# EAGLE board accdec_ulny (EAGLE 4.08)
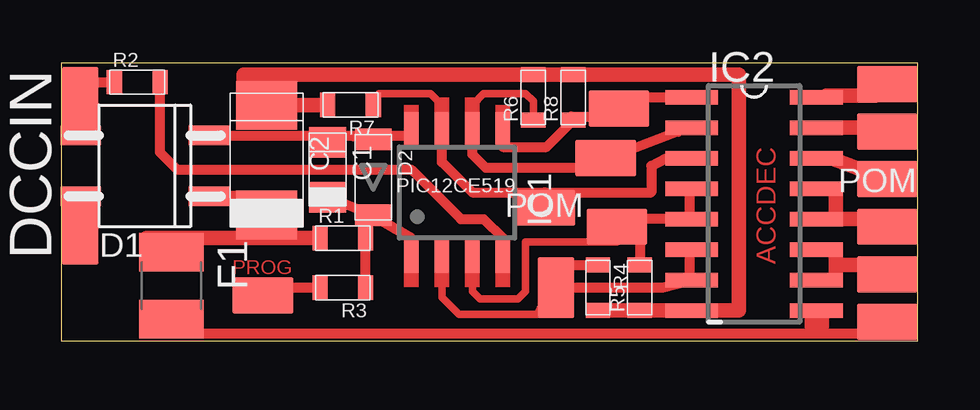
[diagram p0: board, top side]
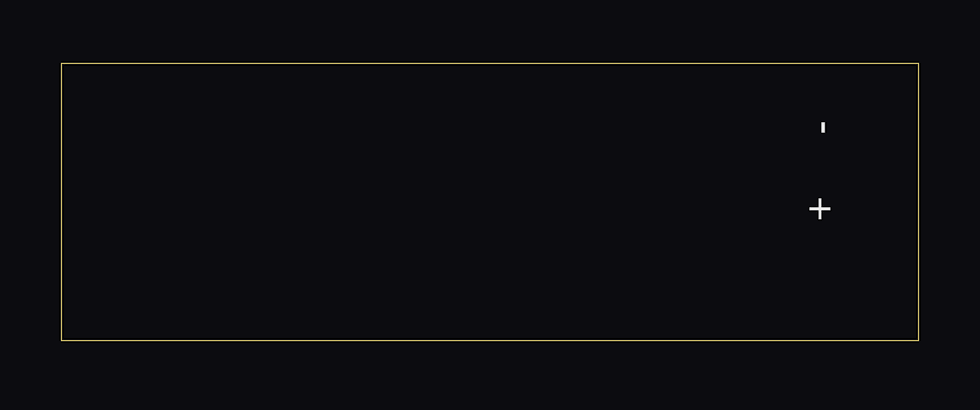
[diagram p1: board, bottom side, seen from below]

Size 35.71 x 11.58 mm. Coordinates in mm from the lower left corner, seen from the top.
Outline: 0,0 35.71,0 35.71,11.58 0,11.58 0,0
Copper layers used: Top

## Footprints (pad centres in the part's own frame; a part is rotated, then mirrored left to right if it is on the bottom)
CON_1*0.6 = smd 2.54 x 1.524: P$1 0,0
CA = smd 1.27 x 1.524: P$1 -1.143,0; P$2 1.143,0
CC = smd 2.032 x 2.54: P$1 -2.286,0; P$2 2.286,0
G1 = smd 1.676 x 0.813: 1 3.302,-1.27; 2 3.302,1.27; 3 -2.032,1.27; 4 -2.032,-1.27
ZMM = smd 0.889 x 1.524: P$1 -1.587,0; P$2 1.587,0
1210 = smd 1.6 x 2.7: 1 -1.4,0; 2 1.4,0
SO8/SN = smd 0.61 x 1.524: 1 -1.905,-2.6; 2 -0.635,-2.6; 3 0.635,-2.6; 4 1.905,-2.6; 5 1.905,2.6; 6 0.635,2.6; 7 -0.635,2.6; 8 -1.905,2.6
SO16 = smd 0.6 x 2.2: 1 -4.445,-2.6; 2 -3.175,-2.6; 3 -1.905,-2.6; 4 -0.635,-2.6; 5 0.635,-2.6; 6 1.905,-2.6; 7 3.175,-2.6; 8 4.445,-2.6; 9 4.445,2.6; 10 3.175,2.6; 11 1.905,2.6; 12 0.635,2.6; 13 -0.635,2.6; 14 -1.905,2.6; 15 -3.175,2.6; 16 -4.445,2.6
MICRO_MELF = smd 0.635 x 1.016: P$1 -0.953,0; P$2 0.953,0

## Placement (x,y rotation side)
+5V  [CON_1*0.6]  8.41,1.9 0 top
+12V  [CON_1*0.6]  34.44,0.79 0 top
C1  2.2µF 6v  [CA]  11.11,7.14 270 top
C2  10µF 25v  [CC]  8.57,7.54 270 top
D1  MB6S  [G1]  2.85,7.3 0 top
D2  5.1v  [ZMM]  13.01,6.82 270 top
DCCIN1  [CON_1*0.6]  0.79,10.15 90 top
DCCIN2  [CON_1*0.6]  0.79,4.44 90 top
F1  500mA  [1210]  4.6,2.3 270 top
IC1  PIC12CE519  [SO8/SN]  16.5,6.19 0 top
IC2  ULN2003A  [SO16]  28.89,5.71 270 top
OUT0  [CON_1*0.6]  34.44,6.74 0 top
OUT1  [CON_1*0.6]  34.44,8.73 0 top
OUT2  [CON_1*0.6]  34.44,10.71 0 top
OUT4  [CON_1*0.6]  34.44,4.76 0 top
OUT5  [CON_1*0.6]  34.44,2.77 0 top
P0  [CON_1*0.6]  20.15,5.55 0 top
P1  [CON_1*0.6]  22.7,7.62 0 top
P2  [CON_1*0.6]  23.25,9.68 0 top
P4  [CON_1*0.6]  23.17,4.76 0 top
P5  [CON_1*0.6]  20.63,2.22 90 top
R1  680  [MICRO_MELF]  11.74,4.28 0 top
R2  100k  [MICRO_MELF]  3.17,10.79 0 top
R3  1k  [MICRO_MELF]  11.74,2.22 180 top
R4  100k  [MICRO_MELF]  22.38,2.22 270 top
R5  100k  [MICRO_MELF]  24.12,2.22 90 top
R6  100k  [MICRO_MELF]  19.68,10.15 90 top
R7  100k  [MICRO_MELF]  12.06,9.84 180 top
R8  100k  [MICRO_MELF]  21.35,10.15 90 top

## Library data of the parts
+5V +12V C1 C2 D1 D2 DCCIN1 DCCIN2 F1 IC1 IC2 OUT0 OUT1 OUT2 OUT4 OUT5 P0 P1 P2 P4 P5 R1-R8 = NMRA-DCC_Decoder_Parts

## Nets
+: C2.P$2 D1.1 F1.1 R1.P$1
DCCIN: IC1.4 R2.P$2
GND: IC2.8 R4.P$2 R5.P$1 R6.P$2 R8.P$2
GP0: IC1.7 P0.P$1 R7.P$1
GP1: IC1.6 R6.P$1
GP2: IC1.5 R8.P$1
GP4: IC1.3 P4.P$1 R5.P$2
GP5: IC1.2 IC2.7 P5.P$1 R4.P$1
N$1: D1.3 DCCIN1.P$1 R2.P$1
N$2: D1.4 DCCIN2.P$1
N$3: +5V.P$1 R3.P$2
N$4: +12V.P$1 F1.2
N$10: OUT0.P$1
N$12: OUT5.P$1
N$14: IC2.14
S$2: IC2.16
S$3: IC2.13
S$8: IC2.4
S$15: C1.P$1 D2.P$1 IC1.8
S$16: C2.P$1 R7.P$2
VCC: C1.P$2 D2.P$2 IC1.1 R1.P$2 R3.P$1

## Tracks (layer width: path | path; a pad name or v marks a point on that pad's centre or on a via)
+
  Top 0.406: 6.58,5.95 D1.1 | F1.1 3.57,4.28 | 8.49,4.28 C2.P$2 8.49,5.95 8.49,4.28
  Top 0.61: 8.49,5.95 6.58,5.95 | 3.57,4.28 8.49,4.28 R1.P$1
DCCIN
  Top 0.406: IC1.4 18.41,4.28 17.61,5.08 16.66,5.08 14.6,7.14 4.84,7.14 4.12,7.85 R2.P$2
GND
  Top 0.406: 26.35,1.27 IC2.8 | 26.35,1.27 R5.P$1 | R6.P$2 11.11,11.11 | R8.P$2 R6.P$2 | R8.P$2 R6.P$2 | R8.P$2 R6.P$2 | 28.25,1.27 26.35,1.27 | 28.25,11.11 R8.P$2 | R4.P$2
  Top 0.61: R8.P$2 11.11,11.11 | R4.P$2 28.25,1.27 28.25,11.11 7.61,11.11 7.61,10.23
GP0
  Top 0.305: 15.87,7.46 15.87,9.84 15.39,10.31 13.25,10.31 13.01,10 R7.P$1
  Top 0.406: 20.15,6.19 P0.P$1 | 20.15,6.19 17.14,6.19 15.87,7.46 IC1.7 | 25.23,7.62 24.6,7.3 24.6,6.19 20.15,6.19
GP1
  Top 0.305: R6.P$1 19.68,10 19.36,10.31 17.61,10.31 17.14,9.84 IC1.6
  Top 0.406: IC1.6 17.14,7.77 17.69,7.22 23.09,7.22
GP2
  Top 0.406: R8.P$1 20.23,8.09 18.41,8.09 IC1.5
GP4
  Top 0.305: P4.P$1 23.17,4.12 19.36,4.12 19.36,2.06 19.04,1.74 17.46,1.74 17.14,2.06 IC1.3
  Top 0.406: R5.P$2 24.12,4.12 23.33,4.76 P4.P$1
GP5
  Top 0.305: IC1.2 15.87,1.82 16.58,1.11 19.84,1.11 | 19.84,1.11 P5.P$1 | 19.84,1.11 20.95,3.17
  Top 0.406: P5.P$1 25.08,2.22 IC2.7 | 20.95,3.17 R4.P$1
N$1
  Top 0.406: R2.P$1 0.79,10.79 DCCIN1.P$1 0.95,8.41 D1.3
N$2
  Top 0.406: D1.4 0.95,4.79 DCCIN2.P$1
N$3
  Top 0.406: R3.P$2 8.41,2.22 +5V.P$1
N$4
  Top 0.406: +12V.P$1 33.65,0.31 5.23,0.31 4.47,0.82 F1.2
N$10
  Top 0.406: OUT0.P$1 34.76,6.98
N$12
  Top 0.406: OUT5.P$1 34.12,2.54
N$14
  Top 0.406: IC2.14 31.58,7.62
S$1
  Top 0.61: 31.9,10.23 33.97,10.23
S$2
  Top 0.406: IC2.16 31.58,10.16
S$3
  Top 0.406: IC2.13 31.58,6.35
S$4
  Top 0.61: 32.06,8.89 33.81,8.89
S$5
  Top 0.61: 32.3,7.54 33.57,7.06
S$6
  Top 0.61: 32.3,3.49 32.3,3.17 | 32.3,3.17 32.3,2.85 | 32.3,3.17 33.57,3.17
S$7
  Top 0.61: 32.3,6.19 32.3,5.08 33.81,5.08
S$8
  Top 0.406: IC2.4 26.03,6.25
S$9
  Top 0.406: 21.27,9.36 23.33,9.36
S$10
  Top 0.406: 24.28,10.16 25.55,10.16
S$11
  Top 0.406: 25.71,8.73 23.65,7.93
S$12
  Top 1.016: 31.51,0.63 31.51,1.03
S$13
  Top 0.406: 26.19,6.35 26.19,5.08 23.96,5.08
S$14
  Top 0.406: 26.19,3.81 26.19,2.54
S$15
  Top 0.305: 10.95,8.57 C1.P$1 | 10.95,8.57 | D2.P$1 10.95,8.57
  Top 0.406: IC1.8 14.6,8.57 10.95,8.57 | 10.95,8.57 | D2.P$1 12.95,8.41 | 6.66,8.57 10.95,8.57
S$16
  Top 0.406: C2.P$1
  Top 0.61: C2.P$1 R7.P$2
VCC
  Top 0.406: D2.P$2 12.69,5.23 R1.P$2 R3.P$1 | D2.P$2 C1.P$2 | IC1.1 14.6,4.28 D2.P$2
(copper drawn outside any net)
  shapes: Top area x8

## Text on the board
Top: ACCDEC | PROG
tPlace: POM | POM | DCCIN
